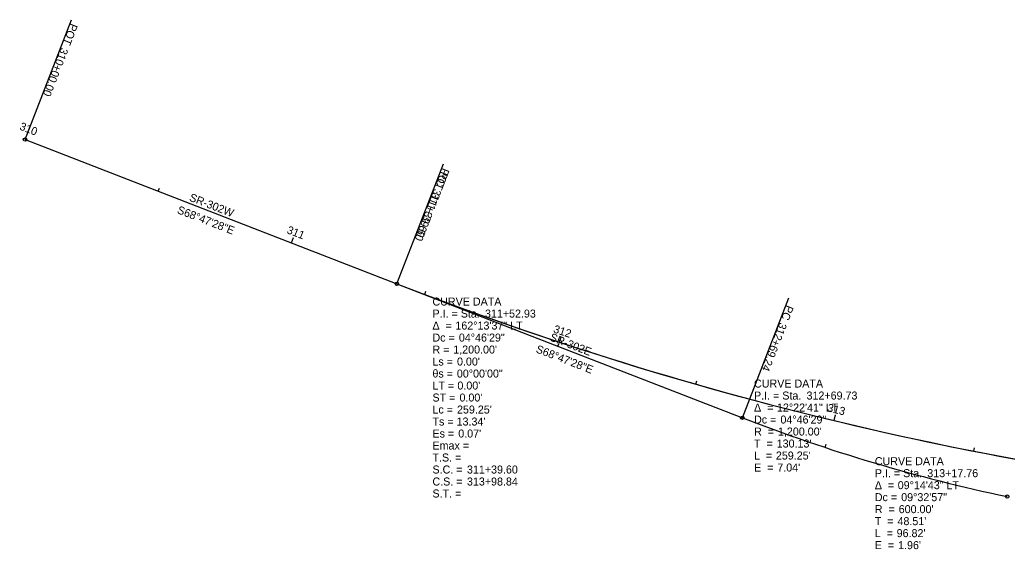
# Model space of a CAD drawing. Extents: x 2047151 to 2048731, y 456453 to 457874.
# Drawn here: x 2047151.3 to 2047496.9, y 457032.9 to 457218.3 of the extents above; entities that cross this region are included whole.
import ezdxf

# ---------------------------------------------------------------- set-up
doc = ezdxf.new("R2010")
doc.units = 0
for name, color, linetype in [('GE_P_Alignment', 7, 'Continuous'), ('GE_P_Alignment_100_Bearings', 7, 'Continuous'), ('GE_P_Alignment_100_Cardinal_Points', 7, 'Continuous'), ('GE_P_Alignment_100_Curve_Data', 7, 'Continuous'), ('GE_P_Alignment_100_Distances', 7, 'Continuous'), ('GE_P_Alignment_100_Stations', 7, 'Continuous'), ('GE_P_Alignment_500_Bearings', 7, 'Continuous'), ('GE_P_Alignment_500_Cardinal_Points', 7, 'Continuous'), ('GE_P_Alignment_500_Curve_Data', 7, 'Continuous'), ('GE_P_Alignment_500_Distances', 7, 'Continuous'), ('GE_P_Alignment_500_Stations', 7, 'Continuous')]:
    doc.layers.add(name, color=color, linetype=linetype)

msp = doc.modelspace()

# ---------------------------------------------------------------- linework, layer by layer
at = {"layer": 'GE_P_Alignment'}
for p, q in [((2047153.18, 457176.36), (2047283.32, 457125.85)), ((2047283.32, 457125.85), (2047404.18, 457078.95)), ((2047283.32, 457125.85), (2047404.18, 457078.95)), ((2047283.32, 457125.85), (2047404.18, 457078.95))]:
    msp.add_line(p, q, dxfattribs=at)
for centre, radius, end in [((2047717.44, 458244.57), 1200, 264.8083), ((2047717.44, 458244.57), 1200, 261.16908), ((2047717.44, 458244.57), 1200, 261.16908), ((2047621.24, 457638.31), 600, 258.03635), ((2047621.24, 457638.31), 600, 258.03635)]:
    msp.add_arc(centre, radius, 248.79098, end, dxfattribs=at)
at = {"layer": 'GE_P_Alignment_100_Cardinal_Points'}
for p, q in [((2047153.18, 457176.36), (2047169.46, 457218.31)), ((2047283.32, 457125.85), (2047299.6, 457167.81))]:
    msp.add_line(p, q, dxfattribs=at)
for centre in [(2047153.18, 457176.36), (2047283.32, 457125.85)]:
    msp.add_circle(centre, 0.6, dxfattribs=at)
at = {"layer": 'GE_P_Alignment_100_Stations'}
for p, q in [((2047153.18, 457176.36), (2047153.9, 457178.22)), ((2047199.79, 457158.27), (2047200.23, 457159.39)), ((2047246.4, 457140.18), (2047247.13, 457142.04)), ((2047293.03, 457122.13), (2047293.46, 457123.25)), ((2047340.16, 457105.43), (2047340.79, 457107.33)), ((2047387.94, 457090.7), (2047388.27, 457091.85)), ((2047436.29, 457077.98), (2047436.75, 457079.92)), ((2047485.12, 457067.28), (2047485.36, 457068.46))]:
    msp.add_line(p, q, dxfattribs=at)
at = {"layer": 'GE_P_Alignment_500_Cardinal_Points'}
for p, q in [((2047283.32, 457125.85), (2047299.6, 457167.81)), ((2047404.18, 457078.95), (2047420.46, 457120.9))]:
    msp.add_line(p, q, dxfattribs=at)
for centre in [(2047283.32, 457125.85), (2047404.18, 457078.95), (2047496.87, 457051.35)]:
    msp.add_circle(centre, 0.6, dxfattribs=at)
at = {"layer": 'GE_P_Alignment_500_Stations'}
for p, q in [((2047339.63, 457104), (2047340.06, 457105.12)), ((2047433.13, 457068.57), (2047433.5, 457069.71))]:
    msp.add_line(p, q, dxfattribs=at)

# ---------------------------------------------------------------- texts
at = {"layer": 'GE_P_Alignment_100_Bearings'}
msp.add_text('S68°47\'28"E', height=2.8, rotation=338.791, dxfattribs=at).set_placement((2047206.19, 457150.64))
at = {"layer": 'GE_P_Alignment_100_Cardinal_Points'}
for s, p in [('POT', (2047169.1, 457217.25)), ('310+00.00', (2047165.79, 457208.73)), ('PC', (2047298.71, 457165.39)), ('311+39.60', (2047296.35, 457159.31))]:
    msp.add_text(s, height=2.8, rotation=248.791, dxfattribs=at).set_placement(p)
at = {"layer": 'GE_P_Alignment_100_Curve_Data'}
for s, p in [('CURVE DATA', (2047295.75, 457118.23)), ('P.I. = Sta. ', (2047295.75, 457114.03)), ('311+52.93', (2047314.12, 457114.03)), ('Δ  = ', (2047295.75, 457109.83)), ('162°13\'37" LT', (2047303.77, 457109.83)), ('04°46\'29"', (2047304.99, 457105.63)), ('Dc = ', (2047295.75, 457105.63)), ('R = ', (2047295.75, 457101.43)), ("1,200.00'", (2047303.03, 457101.43)), ('Ls = ', (2047295.75, 457097.23)), ("0.00'", (2047304.34, 457097.23)), ('θs = ', (2047295.75, 457093.03)), ('00°00\'00"', (2047304.29, 457093.03)), ('LT = ', (2047295.75, 457088.83)), ("0.00'", (2047304.48, 457088.83)), ('CURVE DATA', (2047408.27, 457089.53)), ('P.I. = Sta. ', (2047408.27, 457085.33)), ('312+69.73', (2047426.64, 457085.33)), ('ST = ', (2047295.75, 457084.63)), ("0.00'", (2047305.21, 457084.63)), ('Lc = ', (2047295.75, 457080.43)), ("259.25'", (2047304.34, 457080.43)), ('Δ  = ', (2047408.27, 457081.13)), ('12°22\'41" LT', (2047416.29, 457081.13)), ('Ts = ', (2047295.75, 457076.23)), ("13.34'", (2047304.2, 457076.23)), ('Dc = ', (2047408.27, 457076.93)), ('04°46\'29"', (2047417.51, 457076.93)), ('Es = ', (2047295.75, 457072.03)), ("0.07'", (2047304.78, 457072.03)), ('R  = ', (2047408.27, 457072.73)), ("1,200.00'", (2047416.64, 457072.73)), ('Emax = ', (2047295.75, 457067.83)), ('T  = ', (2047408.27, 457068.53)), ("130.13'", (2047416.2, 457068.53)), ('L  = ', (2047408.27, 457064.33)), ("259.25'", (2047415.92, 457064.33)), ('T.S. = ', (2047295.75, 457063.63)), ('S.C. = ', (2047295.75, 457059.43)), ('311+39.60', (2047307.82, 457059.43)), ('E  = ', (2047408.27, 457060.13)), ("7.04'", (2047416.42, 457060.13)), ('C.S. = ', (2047295.75, 457055.23)), ('313+98.84', (2047307.82, 457055.23)), ('S.T. = ', (2047295.75, 457051.03))]:
    msp.add_text(s, height=2.8, dxfattribs=at).set_placement(p)
at = {"layer": 'GE_P_Alignment_100_Distances'}
msp.add_text('SR-302W', height=2.8, rotation=338.791, dxfattribs=at).set_placement((2047210.43, 457155.02))
at = {"layer": 'GE_P_Alignment_100_Stations'}
for s, rotation, p in [('310', 338.791, (2047151.04, 457179.92)), ('311', 338.791, (2047244.56, 457143.63)), ('312', 341.6751, (2047337.85, 457108.87)), ('313', 346.4497, (2047433.71, 457081.22))]:
    msp.add_text(s, height=2.8, rotation=rotation, dxfattribs=at).set_placement(p)
at = {"layer": 'GE_P_Alignment_500_Bearings'}
msp.add_text('S68°47\'28"E', height=2.8, rotation=338.791, dxfattribs=at).set_placement((2047331.69, 457101.93))
at = {"layer": 'GE_P_Alignment_500_Cardinal_Points'}
for s, p in [('POT', (2047299.18, 457166.61)), ('311+39.60', (2047295.88, 457158.1)), ('PC', (2047419.61, 457118.59)), ('312+69.24', (2047417.25, 457112.51))]:
    msp.add_text(s, height=2.8, rotation=248.791, dxfattribs=at).set_placement(p)
at = {"layer": 'GE_P_Alignment_500_Curve_Data'}
for s, p in [('CURVE DATA', (2047450.53, 457062.35)), ('P.I. = Sta. ', (2047450.53, 457058.15)), ('313+17.76', (2047468.89, 457058.15)), ('Δ  = ', (2047450.53, 457053.95)), ('09°14\'43" LT', (2047458.55, 457053.95)), ('Dc = ', (2047450.53, 457049.75)), ('09°32\'57"', (2047459.76, 457049.75)), ('R  = ', (2047450.53, 457045.55)), ("600.00'", (2047458.89, 457045.55)), ('T  = ', (2047450.53, 457041.35)), ("48.51'", (2047458.46, 457041.35)), ('L  = ', (2047450.53, 457037.15)), ("96.82'", (2047458.17, 457037.15)), ('E  = ', (2047450.53, 457032.95)), ("1.96'", (2047458.68, 457032.95))]:
    msp.add_text(s, height=2.8, dxfattribs=at).set_placement(p)
at = {"layer": 'GE_P_Alignment_500_Distances'}
msp.add_text('SR-302E', height=2.8, rotation=338.791, dxfattribs=at).set_placement((2047336.57, 457106.07))

doc.saveas('drawing.dxf')
